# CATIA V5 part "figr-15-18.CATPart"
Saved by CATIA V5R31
Part number: Part1
Bounding box of the stored display mesh (mm): x -46.56 to 46.56, y -38.965 to 25.965, z 0 to 40
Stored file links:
  D:\PROJECTS\Project 2021\US EDITION\CATIA V5 6R 2021\Resources\Part Files\c15_catia_v5_6r2021_prt\figr-15-18.CATPart
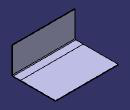
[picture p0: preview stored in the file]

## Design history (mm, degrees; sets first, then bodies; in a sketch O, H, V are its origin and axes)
SheetMetalParameters1: Thickness 1, BendRadius 1, KFactor 0.325257 {= log(min(100,max(20*SheetMetalParameters1.BendRadius,SheetMetalParameters1.Thickness)/SheetMetalParameters1.Thickness))/log(100)/2}, ReliefRadialLength 1, ReliefAxialLength 2, MinimumBendRadius 0
Body1 (main body)
  Sketch1 on xy-plane, origin (0, 0, 0), H (1, 0, 0), V (0, 1, 0)
    line L1 (-46.5596, 25.9646) -> (46.5596, 25.9646)
    line L2 (46.5596, 25.9646) -> (46.5596, -25.9646)
    line L3 (46.5596, -25.9646) -> (-46.5596, -25.9646)
    line L4 (-46.5596, -25.9646) -> (-46.5596, 25.9646)
    horizontal: L1 H, L3 H
    vertical: L2 V, L4 V
    symmetry: L1 L3 H, L4 L2 V
  Wall1: Thickness 1, Profile Sketch1
  d_NewWallOnEdge1: NewWallOnEdge_Edge edge [face of Wall1 | face of Wall1], NewWallOnEdge_Length 40, NewWallOnEdge_HeightLimitOffset 0, NewWallOnEdge_WidthOffset1 0, NewWallOnEdge_WidthOffset2 0, NewWallOnEdge_Angle 90, NewWallOnEdge_BendRadiusValue 1 {= SheetMetalParameters1.BendRadius}, NewWallOnEdge_BendTable SheetMetalParameters1, KFacteur 0.325257 {= log(min(100,max(20*d_NewWallOnEdge1.Radius,SheetMetalParameters1.Thickness)/SheetMetalParameters1.Thickness))/log(100)/2}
